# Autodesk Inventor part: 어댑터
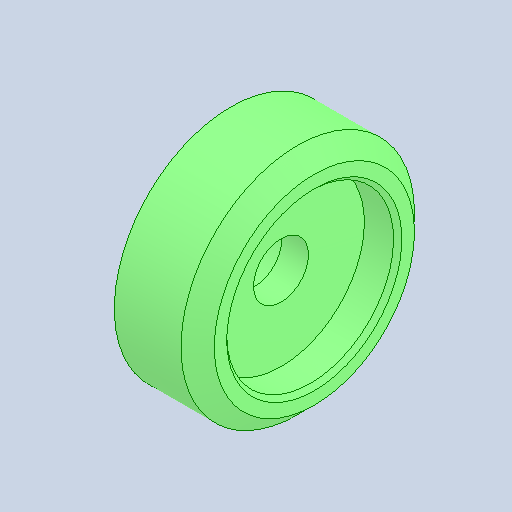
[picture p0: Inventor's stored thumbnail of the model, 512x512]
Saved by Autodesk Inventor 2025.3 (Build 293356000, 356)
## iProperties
Created: 2025-09
Part Number: 어댑터
Material: 강철, 탄소
Document SubType Name: Modeling
Designer: PC-15
Density: 7.85 g/cm^3
Appearance: 기본값
Author: jhkim
Sending System: Autodesk Inventor 2026
Preprocessor: ST-DEVELOPER v20.1
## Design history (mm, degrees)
feature "솔리드1"
node "솔리드2"
